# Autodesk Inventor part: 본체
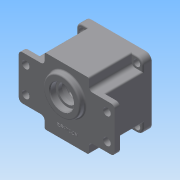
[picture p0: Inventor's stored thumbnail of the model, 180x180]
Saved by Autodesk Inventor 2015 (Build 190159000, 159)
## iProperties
Created: 2015-06
Part Number: 본체
Material: 일반
Document SubType Name: Modeling
Designer: AMC
Density: 1 g/cm^3
Appearance: 기본값
Author: AMC
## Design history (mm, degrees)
sketch "스케치1"
  geometry: L1 (0, 0)-(90, 0); L2 (90, 0)-(90, 90); L3 (90, 90)-(0, 90); L4 (0, 90)-(0, 0)
  constraints: 8 end point, 2 parallel, 1 horizontal, 1 perpendicular
  dimensions: "d0" = 90 distance of L2.end L3.end; "d1" = 90 distance of L1.end L2.end
extrude "돌출1" new body sketch "스케치1" distance "d2" = 12; taper "d3" = 0 deg
sketch "스케치2"
  geometry: L1 (75, 75)-(15, 75); L2 (15, 75)-(15, 15); L3 (15, 15)-(75, 15); L4 (75, 15)-(75, 75); L5 (90, 90)-(0, 90) reference; L6 (90, 0)-(90, 90) reference; 5 further points
  constraints: 8 end point, 4 midpoint, 2 parallel, 1 horizontal, 1 horizontal alignment, 1 perpendicular, 1 vertical alignment
  dimensions: "d4" = 60 distance of L3.end L1.start; "d5" = 60 distance of L1.start L1.end
extrude "돌출2" join sketch "스케치2" distance "d6" = 58; taper "d7" = 0 deg
sketch "스케치3"
  geometry: L1 (75, 75)-(75, 15) reference; L2 (75, 15)-(15, 15) reference; L3 (15, 15)-(15, 75) reference; L4 (15, 75)-(75, 75) reference; L5 (75, 110)-(15, 110); L6 (15, 110)-(15, -20); L7 (15, -20)-(75, -20); L8 (75, -20)-(75, 110); L9 (90, 90)-(0, 90) reference; L10 (90, 0)-(90, 90) reference; 5 further points
  constraints: 8 end point, 4 midpoint, 2 parallel, 1 horizontal, 1 horizontal alignment, 1 perpendicular, 1 vertical alignment
  dimensions: "d8" = 130 distance of L7.end L5.start; "d9" = 60 distance of L5.start L5.end
extrude "돌출3" join sketch "스케치3" distance "d10" = 7; taper "d11" = 0 deg
fillet "모깎기1" dims "d12" = 5
fillet "모깎기2" dims "d13" = 8
fillet "모깎기3" dims "d14" = 5
sketch "스케치4"
  geometry: L1 (15, 20)-(15, 70) reference; L2 (20, 75)-(70, 75) reference; L3 (75, 70)-(75, 20) reference; L4 (70, 15)-(20, 15) reference; L5 (8, 90)-(82, 90) reference; L6 (90, 82)-(90, 8) reference; L7 (82, 0)-(8, 0) reference; L8 (0, 8)-(0, 82) reference; C1 r 4.5 at (82, 82); C2 r 4.5 at (82, 8); C3 r 4.5 at (8, 8); C4 r 4.5 at (8, 82); A1 r 5 centre (20, 20) between (15, 20) and (20, 15) reference; A2 r 5 centre (20, 70) between (20, 75) and (15, 70) reference; A3 r 5 centre (70, 70) between (75, 70) and (70, 75) reference; A4 r 5 centre (70, 20) between (70, 15) and (75, 20) reference; A5 r 8 centre (8, 82) between (8, 90) and (0, 82) reference; A6 r 8 centre (82, 82) between (90, 82) and (82, 90) reference; A7 r 8 centre (82, 8) between (82, 0) and (90, 8) reference; A8 r 8 centre (8, 8) between (0, 8) and (8, 0) reference; 1 further point
  constraints: 4 centre point, 4 coincident
  dimensions: "d15" = 9 diameter of C1; "d16" = 9 diameter of C2; "d17" = 9 diameter of C3; "d18" = 9 diameter of C4
extrude "돌출4" cut sketch "스케치4" distance "d19" = 7; taper "d20" = 0 deg
sketch "스케치5"
  geometry: L1 (75, 105)-(75, -15) reference; L2 (70, -20)-(20, -20) reference; L3 (15, -15)-(15, 105) reference; L4 (20, 110)-(70, 110) reference; L5 (90, 75)-(0, 75); L6 (0, 75)-(0, 15); L7 (0, 15)-(90, 15); L8 (90, 15)-(90, 75); L9 (90, 8)-(90, 82) reference; A1 r 5 centre (70, -15) between (70, -20) and (75, -15) reference; A2 r 5 centre (20, -15) between (15, -15) and (20, -20) reference; A3 r 5 centre (20, 105) between (20, 110) and (15, 105) reference; A4 r 5 centre (70, 105) between (75, 105) and (70, 110) reference; 5 further points
  constraints: 8 end point, 4 midpoint, 2 parallel, 1 coincident, 1 horizontal, 1 perpendicular, 1 vertical alignment
  dimensions: "d21" = 60 distance of L7.end L5.start; "d22" = 90 distance of L6.end L7.end
extrude "돌출5" join sketch "스케치5" stored distance "d23" = 7; taper "d24" = 0 deg
sketch "스케치6"
  geometry: L1 (0, 8)-(0, 15) reference; L2 (0, 15)-(0, 75) reference; L3 (0, 75)-(0, 82) reference; L4 (8, 90)-(82, 90) reference; L5 (90, 82)-(90, 75) reference; L6 (90, 75)-(90, 15) reference; L7 (90, 15)-(90, 8) reference; L8 (82, 0)-(8, 0) reference; L9 (90, 15)-(0, 15) reference; L10 (0, 75)-(90, 75) reference; L11 (75, 90)-(15, 90); L12 (15, 90)-(15, 0); L13 (15, 0)-(75, 0); L14 (75, 0)-(75, 90); C1 r 4.5 at (8, 8) reference; C2 r 4.5 at (82, 82) reference; C3 r 4.5 at (82, 8) reference; C4 r 4.5 at (8, 82) reference; A1 r 8 centre (8, 82) between (8, 90) and (0, 82) reference; A2 r 8 centre (82, 82) between (90, 82) and (82, 90) reference; A3 r 8 centre (82, 8) between (82, 0) and (90, 8) reference; A4 r 8 centre (8, 8) between (0, 8) and (8, 0) reference; 5 further points
  constraints: 8 end point, 4 midpoint, 2 parallel, 1 coincident, 1 horizontal, 1 horizontal alignment, 1 perpendicular
  dimensions: "d25" = 90 distance of L13.end L11.start; "d26" = 60 distance between parallel lines of L12 L14
extrude "돌출6" join sketch "스케치6" stored distance "d27" = 7; taper "d28" = 0 deg
fillet "모깎기4" dims "d29" = 5
sketch "스케치7"
  geometry: L1 (75, 10)-(75, -15) reference; L2 (70, -20)-(20, -20) reference; L3 (15, -15)-(15, 10) reference; L4 (10, 15)-(0, 15) reference; L5 (0, 15)-(0, 75) reference; L6 (0, 75)-(10, 75) reference; L7 (15, 80)-(15, 105) reference; L8 (20, 110)-(70, 110) reference; L9 (75, 105)-(75, 80) reference; L10 (80, 75)-(90, 75) reference; L11 (90, 75)-(90, 15) reference; L12 (90, 15)-(80, 15) reference; C1 r 5.072 at (62.5, 100.571); C2 r 5.147 at (62.5, -9.429); A1 r 5 centre (80, 10) between (80, 15) and (75, 10) reference; A2 r 5 centre (70, -15) between (70, -20) and (75, -15) reference; A3 r 5 centre (20, -15) between (15, -15) and (20, -20) reference; A4 r 5 centre (10, 10) between (15, 10) and (10, 15) reference; A5 r 5 centre (10, 80) between (10, 75) and (15, 80) reference; A6 r 5 centre (20, 105) between (20, 110) and (15, 105) reference; A7 r 5 centre (70, 105) between (75, 105) and (70, 110) reference; A8 r 5 centre (80, 80) between (75, 80) and (80, 75) reference; 1 further point
  constraints: 2 centre point
  dimensions: "d30" = 110 distance of C2.centre C1.centre; "d31" = 12.5 distance from line of C1.centre L9
extrude "돌출7" cut sketch "스케치7" distance "d32" = 7; taper "d33" = 0 deg
node "작업 평면1"
fillet "모깎기5" dims "d34" = 2
node "작업 평면2"
sketch "스케치9"
  geometry: L1 (-8, 70)-(82, 70) reference; L2 (82, 70)-(82, 0) reference; L3 (82, 0)-(-8, 0) reference; L4 (-8, 0)-(-8, 70) reference; L5 (37, 88.411)-(37, -11); L6 (77, 0)-(77, 9); L7 (77, 9)-(76, 9); L8 (76, 9)-(76, 61); L9 (76, 61)-(37, 61); L10 (77, 0)-(37, 0); L11 (37, 61)-(37, 0)
  constraints: 14 end point, 3 vertical, 2 collinear, 2 perpendicular, 1 midpoint, 1 point on line
  dimensions: "d39" = 9 distance of L6.start L6.end; "d40" = 1 distance of L6.end L7.end; "d42" = 52 distance of L7.end L8.end
revolve "회전1" sketch "스케치9" stored, may be unused: angle "d46" = 90 deg
sketch "스케치11"
  geometry: L1 (-30, 35)-(-30, 43) reference; L2 (-28, 45)-(28, 45) reference; L3 (30, 43)-(30, 35) reference; L4 (35, 30)-(43, 30) reference; L5 (45, 28)-(45, -28) reference; L6 (43, -30)-(35, -30) reference; L7 (30, -35)-(30, -43) reference; L8 (28, -45)-(-28, -45) reference; L9 (-30, -43)-(-30, -35) reference; L10 (-35, -30)-(-43, -30) reference; L11 (-45, -28)-(-45, 28) reference; L12 (-43, 30)-(-35, 30) reference; C1 r 39 at (0, 0) reference; C2 r 20.5 at (-11, 0); C3 r 14 at (20, 0); A1 r 5 centre (-35, 35) between (-35, 30) and (-30, 35) reference; A2 r 2 centre (-28, 43) between (-28, 45) and (-30, 43) reference; A3 r 2 centre (28, 43) between (30, 43) and (28, 45) reference; A4 r 5 centre (35, 35) between (30, 35) and (35, 30) reference; A5 r 2 centre (43, 28) between (45, 28) and (43, 30) reference; A6 r 2 centre (43, -28) between (43, -30) and (45, -28) reference; A7 r 5 centre (35, -35) between (35, -30) and (30, -35) reference; A8 r 2 centre (28, -43) between (28, -45) and (30, -43) reference; A9 r 2 centre (-28, -43) between (-30, -43) and (-28, -45) reference; A10 r 5 centre (-35, -35) between (-30, -35) and (-35, -30) reference; A11 r 2 centre (-43, -28) between (-45, -28) and (-43, -30) reference; A12 r 2 centre (-43, 28) between (-43, 30) and (-45, 28) reference; 1 further point
  constraints: 2 centre point
  dimensions: "d54" = 41 diameter of C2; "d55" = 11 distance of C1.centre C2.centre; "d56" = 28 diameter of C3; "d57" = 31 distance of C3.centre C2.centre
extrude "돌출9" join sketch "스케치11" distance "d58" = 7; taper "d59" = 0 deg
sketch "스케치12"
  geometry: L1 (-30, 35)-(-30, 43) reference; L2 (-28, 45)-(28, 45) reference; L3 (30, 43)-(30, 35) reference; L4 (35, 30)-(43, 30) reference; L5 (45, 28)-(45, -28) reference; L6 (43, -30)-(35, -30) reference; L7 (30, -35)-(30, -43) reference; L8 (28, -45)-(-28, -45) reference; L9 (-30, -43)-(-30, -35) reference; L10 (-35, -30)-(-43, -30) reference; L11 (-45, -28)-(-45, 28) reference; L12 (-43, 30)-(-35, 30) reference; C1 r 39 at (0, 0) reference; C2 r 17.5 at (-11, 0); A1 r 20.5 centre (-11, 0) between (6.5, 10.677) and (6.5, -10.677) reference; A2 r 12.5 centre (0, 0) between (9.006, 8.668) and (6.5, 10.677) reference; A3 r 14 centre (20, 0) between (9.006, -8.668) and (9.006, 8.668) reference; A4 r 12.5 centre (0, 0) between (6.5, -10.677) and (9.006, -8.668) reference; A5 r 5 centre (-35, 35) between (-35, 30) and (-30, 35) reference; A6 r 2 centre (-28, 43) between (-28, 45) and (-30, 43) reference; A7 r 2 centre (28, 43) between (30, 43) and (28, 45) reference; A8 r 5 centre (35, 35) between (30, 35) and (35, 30) reference; A9 r 2 centre (43, 28) between (45, 28) and (43, 30) reference; A10 r 2 centre (43, -28) between (43, -30) and (45, -28) reference; A11 r 5 centre (35, -35) between (35, -30) and (30, -35) reference; A12 r 2 centre (28, -43) between (28, -45) and (30, -43) reference; A13 r 2 centre (-28, -43) between (-30, -43) and (-28, -45) reference; A14 r 5 centre (-35, -35) between (-30, -35) and (-35, -30) reference; A15 r 2 centre (-43, -28) between (-45, -28) and (-43, -30) reference; A16 r 2 centre (-43, 28) between (-43, 30) and (-45, 28) reference; 1 further point
  constraints: 1 centre point, 1 coincident
  dimensions: "d60" = 35 diameter of C2
extrude "돌출10" cut sketch "스케치12" distance "d61" = 10; taper "d62" = 0 deg
node "작업 평면3"
sketch "스케치13"
  geometry: L1 (90, 17)-(90, 73) reference; L2 (20, 110)-(70, 110) reference; L3 (45, 110)-(45, -25.853); C1 r 25 at (56, 45); 2 further points
  constraints: 2 end point, 2 midpoint, 1 centre point, 1 horizontal alignment, 1 vertical
  dimensions: "d63" = 50 diameter of C1; "d65" = 11 distance from line of L3 C1.centre
extrude "돌출11" join sketch "스케치13" distance "d66" = 7; taper "d67" = 0 deg
hole "구멍2" diameter "d70" = 25; stored, may be unused: countersink angle "d74" = 90 deg, drill point angle "d76" = 118 deg; dims "d68" = 10, "d69" = 10, "d71" = 6, "d72" = 32, "d73" = 8, "d75" = 8
sketch "스케치14"
  geometry: L1 (-30, 35)-(-30, 43) reference; L2 (-28, 45)-(28, 45) reference; L3 (30, 43)-(30, 35) reference; L4 (35, 30)-(43, 30) reference; L5 (45, 28)-(45, -28) reference; L6 (43, -30)-(35, -30) reference; L7 (30, -35)-(30, -43) reference; L8 (28, -45)-(-28, -45) reference; L9 (-30, -43)-(-30, -35) reference; L10 (-35, -30)-(-43, -30) reference; L11 (-45, -28)-(-45, 28) reference; L12 (-43, 30)-(-35, 30) reference; C1 r 12.5 at (-11, 0) reference; C2 r 39 at (0, 0) reference; C3 r 20.5 at (-11, 0); C4 r 14 at (20, 0); A1 r 5 centre (-35, 35) between (-35, 30) and (-30, 35) reference; A2 r 2 centre (-28, 43) between (-28, 45) and (-30, 43) reference; A3 r 2 centre (28, 43) between (30, 43) and (28, 45) reference; A4 r 5 centre (35, 35) between (30, 35) and (35, 30) reference; A5 r 2 centre (43, 28) between (45, 28) and (43, 30) reference; A6 r 2 centre (43, -28) between (43, -30) and (45, -28) reference; A7 r 5 centre (35, -35) between (35, -30) and (30, -35) reference; A8 r 2 centre (28, -43) between (28, -45) and (30, -43) reference; A9 r 2 centre (-28, -43) between (-30, -43) and (-28, -45) reference; A10 r 5 centre (-35, -35) between (-30, -35) and (-35, -30) reference; A11 r 2 centre (-43, -28) between (-45, -28) and (-43, -30) reference; A12 r 2 centre (-43, 28) between (-43, 30) and (-45, 28) reference; 1 further point
  constraints: 2 centre point, 1 coincident
  dimensions: "d77" = 41 diameter of C3; "d78" = 31 distance of C4.centre C1.centre; "d79" = 28 diameter of C4
extrude "돌출12" join sketch "스케치14" distance "d80" = 7; taper "d81" = 0 deg
sketch "스케치15"
  geometry: L1 (-30, 35)-(-30, 43) reference; L2 (-28, 45)-(28, 45) reference; L3 (30, 43)-(30, 35) reference; L4 (35, 30)-(43, 30) reference; L5 (45, 28)-(45, -28) reference; L6 (43, -30)-(35, -30) reference; L7 (30, -35)-(30, -43) reference; L8 (28, -45)-(-28, -45) reference; L9 (-30, -43)-(-30, -35) reference; L10 (-35, -30)-(-43, -30) reference; L11 (-45, -28)-(-45, 28) reference; L12 (-43, 30)-(-35, 30) reference; C1 r 12.5 at (-11, 0) reference; C2 r 39 at (0, 0) reference; C3 r 17.5 at (-11, 0); A1 r 20.5 centre (-11, 0) between (8.117, 7.402) and (8.117, -7.402) reference; A2 r 14 centre (20, 0) between (8.117, -7.402) and (8.117, 7.402) reference; A3 r 5 centre (-35, 35) between (-35, 30) and (-30, 35) reference; A4 r 2 centre (-28, 43) between (-28, 45) and (-30, 43) reference; A5 r 2 centre (28, 43) between (30, 43) and (28, 45) reference; A6 r 5 centre (35, 35) between (30, 35) and (35, 30) reference; A7 r 2 centre (43, 28) between (45, 28) and (43, 30) reference; A8 r 2 centre (43, -28) between (43, -30) and (45, -28) reference; A9 r 5 centre (35, -35) between (35, -30) and (30, -35) reference; A10 r 2 centre (28, -43) between (28, -45) and (30, -43) reference; A11 r 2 centre (-28, -43) between (-30, -43) and (-28, -45) reference; A12 r 5 centre (-35, -35) between (-30, -35) and (-35, -30) reference; A13 r 2 centre (-43, -28) between (-45, -28) and (-43, -30) reference; A14 r 2 centre (-43, 28) between (-43, 30) and (-45, 28) reference; 1 further point
  constraints: 1 centre point, 1 coincident
  dimensions: "d82" = 35 diameter of C3
extrude "돌출13" cut sketch "스케치15" distance "d83" = 10; taper "d84" = 0 deg
sketch "스케치16"
  geometry: L1 (-30, 35)-(-30, 43) reference; L2 (-28, 45)-(28, 45) reference; L3 (30, 43)-(30, 35) reference; L4 (35, 30)-(43, 30) reference; L5 (45, 28)-(45, -28) reference; L6 (43, -30)-(35, -30) reference; L7 (30, -35)-(30, -43) reference; L8 (28, -45)-(-28, -45) reference; L9 (-30, -43)-(-30, -35) reference; L10 (-35, -30)-(-43, -30) reference; L11 (-45, -28)-(-45, 28) reference; L12 (-43, 30)-(-35, 30) reference; C1 r 17.5 at (-11, 0) reference; C2 r 39 at (0, 0) reference; C3 r 11 at (20, 0); A1 r 20.5 centre (-11, 0) between (8.117, 7.402) and (8.117, -7.402) reference; A2 r 14 centre (20, 0) between (8.117, -7.402) and (8.117, 7.402) reference; A3 r 5 centre (-35, 35) between (-35, 30) and (-30, 35) reference; A4 r 2 centre (-28, 43) between (-28, 45) and (-30, 43) reference; A5 r 2 centre (28, 43) between (30, 43) and (28, 45) reference; A6 r 5 centre (35, 35) between (30, 35) and (35, 30) reference; A7 r 2 centre (43, 28) between (45, 28) and (43, 30) reference; A8 r 2 centre (43, -28) between (43, -30) and (45, -28) reference; A9 r 5 centre (35, -35) between (35, -30) and (30, -35) reference; A10 r 2 centre (28, -43) between (28, -45) and (30, -43) reference; A11 r 2 centre (-28, -43) between (-30, -43) and (-28, -45) reference; A12 r 5 centre (-35, -35) between (-30, -35) and (-35, -30) reference; A13 r 2 centre (-43, -28) between (-45, -28) and (-43, -30) reference; A14 r 2 centre (-43, 28) between (-43, 30) and (-45, 28) reference; 1 further point
  constraints: 1 centre point, 1 coincident
  dimensions: "d85" = 22 diameter of C3
extrude "돌출14" cut sketch "스케치16" distance "d86" = 7; taper "d87" = 0 deg
sketch "스케치17"
  geometry: L1 (-50, 35)-(-50, 43) reference; L2 (-48, 45)-(8, 45) reference; L3 (10, 43)-(10, 35) reference; L4 (15, 30)-(23, 30) reference; L5 (25, 28)-(25, -28) reference; L6 (23, -30)-(15, -30) reference; L7 (10, -35)-(10, -43) reference; L8 (8, -45)-(-48, -45) reference; L9 (-50, -43)-(-50, -35) reference; L10 (-55, -30)-(-63, -30) reference; L11 (-65, -28)-(-65, 28) reference; L12 (-63, 30)-(-55, 30) reference; C1 r 11 at (0, 0) reference; C2 r 17.5 at (-31, 0) reference; C3 r 39 at (-20, 0) reference; C4 r 9.5 at (0, 0); A1 r 20.5 centre (-31, 0) between (-11.883, 7.402) and (-11.883, -7.402) reference; A2 r 14 centre (0, 0) between (-11.883, -7.402) and (-11.883, 7.402) reference; A3 r 5 centre (-55, 35) between (-55, 30) and (-50, 35) reference; A4 r 2 centre (-48, 43) between (-48, 45) and (-50, 43) reference; A5 r 2 centre (8, 43) between (10, 43) and (8, 45) reference; A6 r 5 centre (15, 35) between (10, 35) and (15, 30) reference; A7 r 2 centre (23, 28) between (25, 28) and (23, 30) reference; A8 r 2 centre (23, -28) between (23, -30) and (25, -28) reference; A9 r 5 centre (15, -35) between (15, -30) and (10, -35) reference; A10 r 2 centre (8, -43) between (8, -45) and (10, -43) reference; A11 r 2 centre (-48, -43) between (-50, -43) and (-48, -45) reference; A12 r 5 centre (-55, -35) between (-50, -35) and (-55, -30) reference; A13 r 2 centre (-63, -28) between (-65, -28) and (-63, -30) reference; A14 r 2 centre (-63, 28) between (-63, 30) and (-65, 28) reference; 1 further point
  constraints: 1 centre point, 1 coincident
  dimensions: "d88" = 19 diameter of C4
extrude "돌출15" cut sketch "스케치17" distance "d89" = 1; taper "d90" = 0 deg
sketch "스케치18" dims "d91" = 70
  geometry: L1 (-30, 35)-(-30, 43) reference; L2 (-28, 45)-(28, 45) reference; L3 (30, 43)-(30, 35) reference; L4 (35, 30)-(43, 30) reference; L5 (45, 28)-(45, -28) reference; L6 (43, -30)-(35, -30) reference; L7 (30, -35)-(30, -43) reference; L8 (28, -45)-(-28, -45) reference; L9 (-30, -43)-(-30, -35) reference; L10 (-35, -30)-(-43, -30) reference; L11 (-45, -28)-(-45, 28) reference; L12 (-43, 30)-(-35, 30) reference; L13 (0, 0)-(38.536, -38.536); L14 (0, 0)-(54.497, 0); L15 (26.331, -21.075)-(35.701, -25.112); L16 (23.543, -36.581)-(20.865, -25.705); L17 (19.284, -19.284)-(19.237, -19.093); C1 r 9.5 at (20, 0) reference; C2 r 11 at (20, 0) reference; C3 r 17.5 at (-11, 0) reference; C4 r 39 at (0, 0) reference; A1 r 20.5 centre (-11, 0) between (8.117, 7.402) and (8.117, -7.402) reference; A2 r 14 centre (20, 0) between (8.117, -7.402) and (8.117, 7.402) reference; A3 r 5 centre (-35, 35) between (-35, 30) and (-30, 35) reference; A4 r 2 centre (-28, 43) between (-28, 45) and (-30, 43) reference; A5 r 2 centre (28, 43) between (30, 43) and (28, 45) reference; A6 r 5 centre (35, 35) between (30, 35) and (35, 30) reference; A7 r 2 centre (43, 28) between (45, 28) and (43, 30) reference; A8 r 2 centre (43, -28) between (43, -30) and (45, -28) reference; A9 r 5 centre (35, -35) between (35, -30) and (30, -35) reference; A10 r 2 centre (28, -43) between (28, -45) and (30, -43) reference; A11 r 2 centre (-28, -43) between (-30, -43) and (-28, -45) reference; A12 r 5 centre (-35, -35) between (-30, -35) and (-35, -30) reference; A13 r 2 centre (-43, -28) between (-45, -28) and (-43, -30) reference; A14 r 2 centre (-43, 28) between (-43, 30) and (-45, 28) reference; A15 r 4 centre (24.749, -24.749) between (20.865, -25.705) and (26.331, -21.075); A16 r 39 centre (0, 0) between (22.397, -31.928) and (39, 0); 1 further point
  constraints: 10 end point, 5 point on circle, 4 point on line, 3 tangent, 2 centre point, 2 coincident, 1 equal length, 1 horizontal, 3 other
  dimensions: "d92" = 45 deg angle of L13 L14; "d93" = 8 diameter of A15
extrude "돌출16" join sketch "스케치18" distance "d94" = 52; taper "d95" = 0 deg
sketch "스케치19"
  geometry: L1 (-30, 35)-(-30, 43) reference; L2 (-28, 45)-(28, 45) reference; L3 (30, 43)-(30, 35) reference; L4 (35, 30)-(43, 30) reference; L5 (45, 28)-(45, -28) reference; L6 (43, -30)-(35, -30) reference; L7 (30, -35)-(30, -43) reference; L8 (28, -45)-(-28, -45) reference; L9 (-30, -43)-(-30, -35) reference; L10 (-35, -30)-(-43, -30) reference; L11 (-45, -28)-(-45, 28) reference; L12 (-43, 30)-(-35, 30) reference; L13 (23.419, -31.186)-(21.148, -26.49); L14 (25.68, -20.859)-(31.954, -22.36); C1 r 9.5 at (20, 0) reference; C2 r 11 at (20, 0) reference; C3 r 17.5 at (-11, 0) reference; A1 r 4 centre (24.749, -24.749) between (27.577, -27.577) and (21.148, -26.49) reference; A2 r 39 centre (0, 0) between (27.577, -27.577) and (31.954, -22.36) reference; A3 r 20.5 centre (-11, 0) between (8.117, 7.402) and (8.117, -7.402) reference; A4 r 14 centre (20, 0) between (8.117, -7.402) and (8.117, 7.402) reference; A5 r 5 centre (-35, 35) between (-35, 30) and (-30, 35) reference; A6 r 2 centre (-28, 43) between (-28, 45) and (-30, 43) reference; A7 r 2 centre (28, 43) between (30, 43) and (28, 45) reference; A8 r 5 centre (35, 35) between (30, 35) and (35, 30) reference; A9 r 2 centre (43, 28) between (45, 28) and (43, 30) reference; A10 r 2 centre (43, -28) between (43, -30) and (45, -28) reference; A11 r 5 centre (35, -35) between (35, -30) and (30, -35) reference; A12 r 2 centre (28, -43) between (28, -45) and (30, -43) reference; A13 r 2 centre (-28, -43) between (-30, -43) and (-28, -45) reference; A14 r 5 centre (-35, -35) between (-30, -35) and (-35, -30) reference; A15 r 2 centre (-43, -28) between (-45, -28) and (-43, -30) reference; A16 r 2 centre (-43, 28) between (-43, 30) and (-45, 28) reference; A17 r 39 centre (0, 0) between (23.419, -31.186) and (31.954, -22.36); 1 further point
  constraints: 7 point on circle, 4 end point, 2 tangent, 1 centre point
extrude "돌출17" join sketch "스케치19" distance "d96" = 52; taper "d97" = 0 deg
fillet "모깎기6" dims "d98" = 2
sketch "스케치20"
  geometry: L1 (22.686, -29.671)-(21.148, -26.49) reference; L2 (25.68, -20.859)-(30.604, -22.037) reference; L3 (29.671, 22.686)-(26.49, 21.148) reference; L4 (20.859, 25.68)-(22.037, 30.604) reference; L5 (-22.686, 29.671)-(-21.148, 26.49) reference; L6 (-25.68, 20.859)-(-30.604, 22.037) reference; L7 (-29.671, -22.686)-(-26.49, -21.148) reference; L8 (-20.859, -25.68)-(-22.037, -30.604) reference; L9 (-45, -37)-(-45, 37) reference; L10 (-37, 45)-(37, 45) reference; L11 (45, 37)-(45, -37) reference; L12 (37, -45)-(-37, -45) reference; C1 r 40 at (0, 0) reference; C2 r 4.5 at (37, -37) reference; C3 r 4.5 at (-37, 37) reference; C4 r 4.5 at (-37, -37) reference; C5 r 4.5 at (37, 37) reference; A1 r 2 centre (-20.092, -31.07) between (-22.037, -30.604) and (-21.178, -32.749) reference; A2 r 39 centre (0, 0) between (-21.178, -32.749) and (22.015, -32.192) reference; A3 r 2 centre (20.886, -30.542) between (22.015, -32.192) and (22.686, -29.671) reference; A4 r 4 centre (24.749, -24.749) between (25.68, -20.859) and (21.148, -26.49) reference; A5 r 2 centre (31.07, -20.092) between (30.604, -22.037) and (32.749, -21.178) reference; A6 r 39 centre (0, 0) between (32.749, -21.178) and (32.192, 22.015) reference; A7 r 2 centre (30.542, 20.886) between (32.192, 22.015) and (29.671, 22.686) reference; A8 r 4 centre (24.749, 24.749) between (20.859, 25.68) and (26.49, 21.148) reference; A9 r 2 centre (20.092, 31.07) between (22.037, 30.604) and (21.178, 32.749) reference; A10 r 39 centre (0, 0) between (21.178, 32.749) and (-22.015, 32.192) reference; A11 r 2 centre (-20.886, 30.542) between (-22.015, 32.192) and (-22.686, 29.671) reference; A12 r 4 centre (-24.749, 24.749) between (-25.68, 20.859) and (-21.148, 26.49) reference; A13 r 2 centre (-31.07, 20.092) between (-30.604, 22.037) and (-32.749, 21.178) reference; A14 r 39 centre (0, 0) between (-32.749, 21.178) and (-32.192, -22.015) reference; A15 r 2 centre (-30.542, -20.886) between (-32.192, -22.015) and (-29.671, -22.686) reference; A16 r 4 centre (-24.749, -24.749) between (-20.859, -25.68) and (-26.49, -21.148) reference; A17 r 8 centre (-37, 37) between (-37, 45) and (-45, 37) reference; A18 r 8 centre (37, 37) between (45, 37) and (37, 45) reference; A19 r 8 centre (37, -37) between (37, -45) and (45, -37) reference; A20 r 8 centre (-37, -37) between (-45, -37) and (-37, -45) reference; 5 further points
  constraints: 4 coincident
hole "구멍3" sketch "스케치20" at (24.749, 24.749), (-24.749, 24.749), (-24.749, -24.749), (24.749, -24.749) diameter "d102" = 3.242; stored, may be unused: countersink angle "d106" = 90 deg, drill point angle "d108" = 118 deg; dims "d103" = 12, "d104" = 22, "d105" = 7, "d107" = 15
fillet "모깎기7" dims "d109" = 2
fillet "모깎기8" dims "d110" = 0.3
fillet "모깎기9" dims "d111" = 2
fillet "모깎기10" dims "d112" = 0.3
chamfer "모따기1" distance "d113" = 1; stored, may be unused: second distance "d114" = 2, angle "d115" = 45 deg
fillet "모깎기11" dims "d116" = 2
node "작업 평면4"
sketch "스케치21"
  geometry: L1 (0, 73)-(0, 17) reference; 2 further points
  constraints: 1 other
  dimensions: "d118" = 15 distance from line of L1 point (15, 43.868)
feature "엠보싱1" sketch "스케치21" dims "d119" = 0.5, "d120" = 0
node "솔리드1"
mirror "대칭1"
pattern_circular "원형 패턴1" dims "d100" = 360 deg
node "절단 모서리 투영1"
node "절단 모서리 투영2"
node "절단 모서리 투영3"
node "절단 모서리 투영4"
node "절단 모서리 투영5"
node "절단 모서리 투영6"
node "절단 모서리 투영8"
node "절단 모서리 투영9"
node "절단 모서리 투영10"
node "절단 모서리 투영11"
node "절단 모서리 투영12"
node "절단 모서리 투영13"
node "절단 모서리 투영14"
node "절단 모서리 투영15"
node "절단 모서리 투영16"
